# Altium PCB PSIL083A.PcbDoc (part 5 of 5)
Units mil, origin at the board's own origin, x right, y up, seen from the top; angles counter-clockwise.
Board outline 8750 x 2700 mil, 4 copper layers (Top Layer, Signal Layer 1, Signal Layer 2, Bottom Layer), stack 61.2 mil thick; 463 components, 395 nets, 2267 pads, 745 vias.
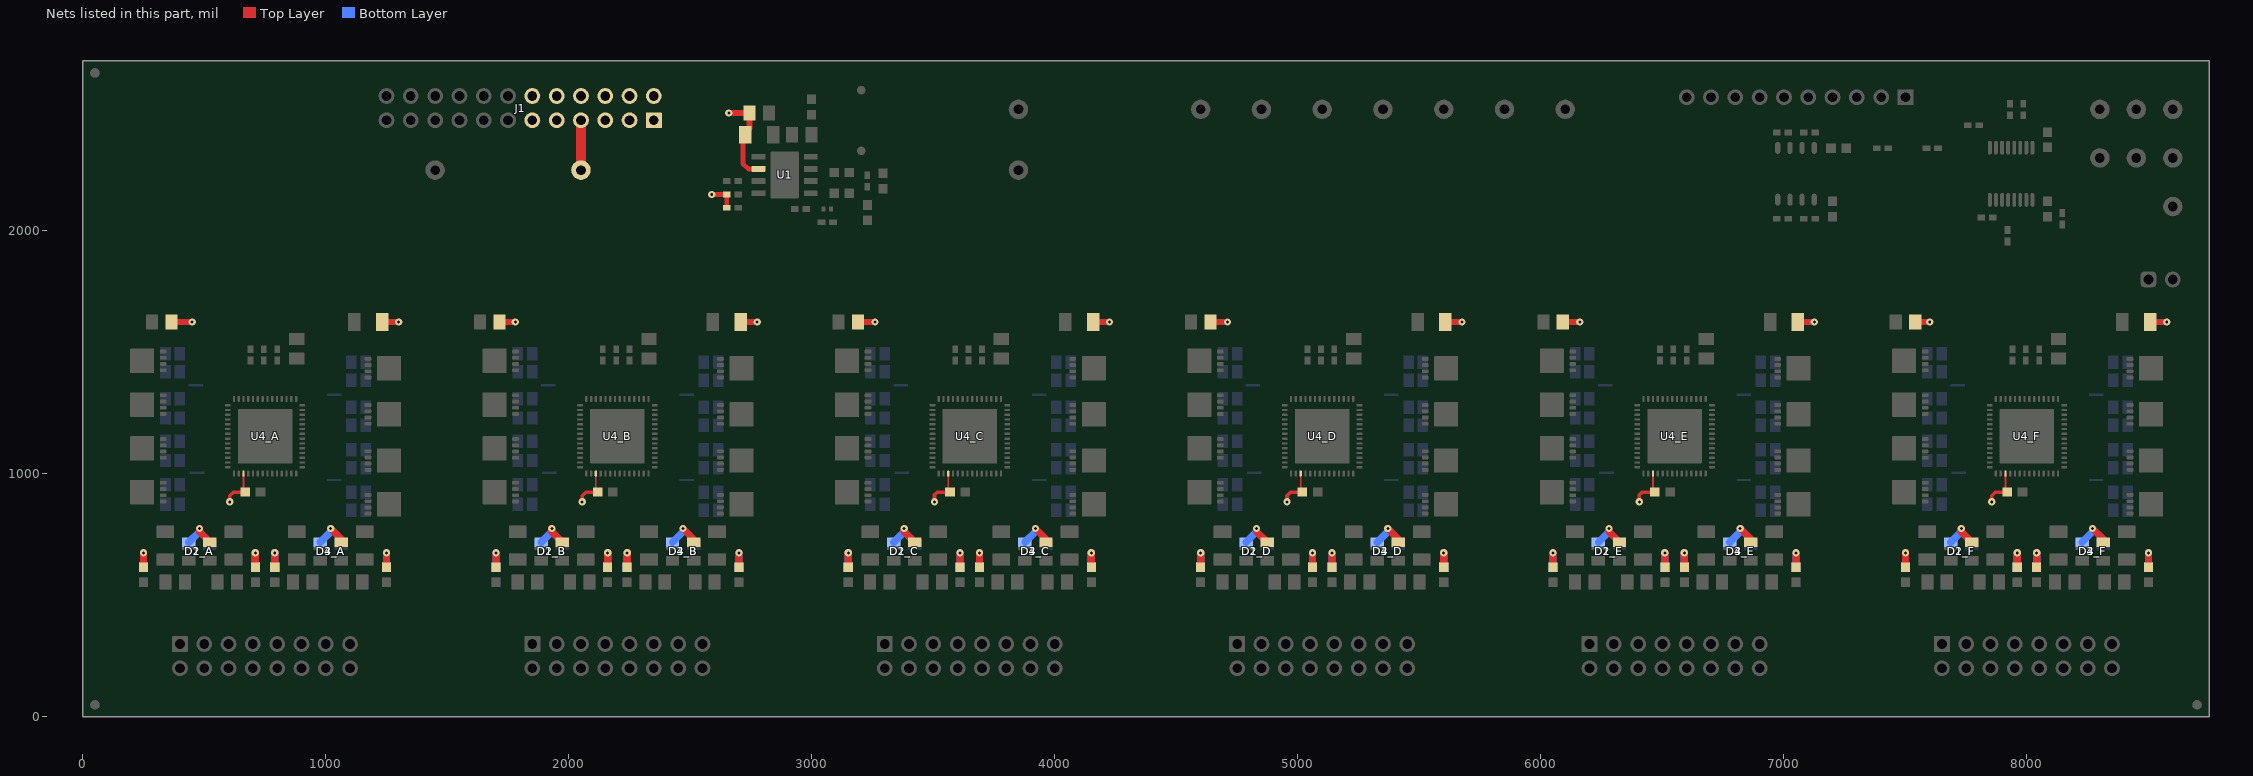
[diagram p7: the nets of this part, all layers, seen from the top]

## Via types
v1: diameter 30, hole 12, Top Layer to Bottom Layer, 610 vias
v2: diameter 19.68, hole 7.87, Top Layer to Bottom Layer, 130 vias
v3: diameter 19.68, hole 7.87, Top Layer to Bottom Layer, tented both sides, 4 vias
v4: diameter 34, hole 16, Top Layer to Bottom Layer, 1 vias

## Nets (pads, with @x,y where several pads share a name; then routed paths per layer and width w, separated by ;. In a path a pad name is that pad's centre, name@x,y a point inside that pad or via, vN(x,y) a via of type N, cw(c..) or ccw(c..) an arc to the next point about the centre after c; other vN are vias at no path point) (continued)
VPWR: C2.2 C3.2 C4.2 C5.2 C13_A.1 C13_B.1 C13_C.1 C13_D.1 C13_E.1 C13_F.1 C25.2 C26.2 C27.2 C28.2 C29.2 C30.2 C31.2 C32.2 C33.2 C34.2 D1_A.4 D1_B.4 D1_C.4 D1_D.4 D1_E.4 D1_F.4 D2_A.4 D2_B.4 D2_C.4 D2_D.4 D2_E.4 D2_F.4 D3_A.4 D3_B.4 D3_C.4 D3_D.4 D3_E.4 D3_F.4 D4_A.4 D4_B.4 D4_C.4 D4_D.4 D4_E.4 D4_F.4 J1.1 J1.2 J1.3 J1.4 J1.5 J1.6 J1.7 J1.8 J1.9 J1.10 J1.11 J1.12 L2_A.1 L2_B.1 L2_C.1 L2_D.1 L2_E.1 L2_F.1 L3_A.1 L3_B.1 L3_C.1 L3_D.1 L3_E.1 L3_F.1 L4_A.1 L4_B.1 L4_C.1 L4_D.1 L4_E.1 L4_F.1 L5_A.1 L5_B.1 L5_C.1 L5_D.1 L5_E.1 L5_F.1 L6_A.1 L6_B.1 L6_C.1 L6_D.1 L6_E.1 L6_F.1 L7_A.1 L7_B.1 L7_C.1 L7_D.1 L7_E.1 L7_F.1 L8_A.1 L8_B.1 L8_C.1 L8_D.1 L8_E.1 L8_F.1 L9_A.1 L9_B.1 L9_C.1 L9_D.1 L9_E.1 L9_F.1 R1.1 R2.1 TP1.1 U1.2 U4_A.17 U4_B.17 U4_C.17 U4_D.17 U4_E.17 U4_F.17 | length 7036.7
  Top Layer w7: U4_A.17@661.42,1001.46 661.42,932.09 C13_A.1@668.5,925 ; U4_B.17@2111.42,1001.46 2111.42,932.09 C13_B.1@2118.5,925 ; U4_C.17@3561.42,1001.46 3561.42,932.09 C13_C.1@3568.5,925 ; U4_D.17@5011.42,1001.46 5011.42,932.09 C13_D.1@5018.5,925 ; U4_E.17@6461.42,1001.46 6461.42,932.09 C13_E.1@6468.5,925 ; U4_F.17@7911.42,1001.46 7911.42,932.09 C13_F.1@7918.5,925
  Top Layer w15: v1(605,885) 605,910 620,925 C13_A.1@668.5,925 ; v1(2055,885) 2055,910 2070,925 C13_B.1@2118.5,925 ; v1(3505,885) 3505,914.51 3515.49,925 C13_C.1@3568.5,925 ; v1(4955,885) 4955,910 4970,925 C13_D.1@5018.5,925 ; v1(6405,885) 6405,914.51 6415.49,925 C13_E.1@6468.5,925 ; v1(7855,885) 7855,910 7870,925 C13_F.1@7918.5,925
  Top Layer w20: v1(2588.31,2150) R2.1@2649.69,2150 R1.1@2649.69,2095 ; C5.2@2716.38,2395 2716.38,2276.93 2738.31,2255 U1.2@2781.02,2255
  Top Layer w25: C3.2@365,1625 v1(450,1625) ; C2.2@1241.93,1625 v1(1300,1625) ; C26.2@1715,1625 v1(1780,1625) ; v1(2658.31,2485) C4.2@2743.31,2485 2743.31,2421.93 C5.2@2716.38,2395 ; C25.2@2716.93,1625 v1(2775,1625) ; C28.2@3190,1625 v1(3260,1625) ; C27.2@4166.93,1625 v1(4225,1625) ; C30.2@4640,1625 v1(4710,1625) ; C29.2@5616.93,1625 v1(5675,1625) ; C32.2@6090,1625 v1(6160,1625) ; C31.2@7066.93,1625 v1(7125,1625) ; C34.2@7540,1625 v1(7600,1625) ; C33.2@8516.93,1625 v1(8575,1625)
  Top Layer w30: L4_A.1@250,616.5 v1(250,675) ; v1(480,775) 480,761.61 D2_A.4@523.31,718.31 ; L5_A.1@710,616.5 v1(710,675) ; L8_A.1@790,616.5 v1(790,675) ; v1(1020,775) 1063.31,731.69 D4_A.4@1063.31,718.31 ; L9_A.1@1250,616.5 v1(1250,675) ; L4_B.1@1700,616.5 v1(1700,675) ; v1(1930,775) 1930,761.61 D2_B.4@1973.31,718.31 ; L5_B.1@2160,616.5 v1(2160,675) ; L8_B.1@2240,616.5 v1(2240,675) ; v1(2470,775) 2513.31,731.69 D4_B.4@2513.31,718.31 ; L9_B.1@2700,616.5 v1(2700,675) ; L4_C.1@3150,616.5 v1(3150,675) ; v1(3380,775) 3380,761.61 D2_C.4@3423.31,718.31 ; L5_C.1@3610,616.5 v1(3610,675) ; L8_C.1@3690,616.5 v1(3690,675) ; v1(3920,775) 3963.31,731.69 D4_C.4@3963.31,718.31 ; L9_C.1@4150,616.5 v1(4150,675) ; L4_D.1@4600,616.5 v1(4600,675) ; v1(4830,775) 4830,761.61 D2_D.4@4873.31,718.31 ; L5_D.1@5060,616.5 v1(5060,675) ; L8_D.1@5140,616.5 v1(5140,675) ; v1(5370,775) 5413.31,731.69 D4_D.4@5413.31,718.31 ; L9_D.1@5600,616.5 v1(5600,675) ; L4_E.1@6050,616.5 v1(6050,675) ; v1(6280,775) 6280,761.61 D2_E.4@6323.31,718.31 ; L5_E.1@6510,616.5 v1(6510,675) ; L8_E.1@6590,616.5 v1(6590,675) ; v1(6820,775) 6863.31,731.69 D4_E.4@6863.31,718.31 ; L9_E.1@7050,616.5 v1(7050,675) ; L4_F.1@7500,616.5 v1(7500,675) ; v1(7730,775) 7730,761.61 D2_F.4@7773.31,718.31 ; L5_F.1@7960,616.5 v1(7960,675) ; L8_F.1@8040,616.5 v1(8040,675) ; v1(8270,775) 8313.31,731.69 D4_F.4@8313.31,718.31 ; L9_F.1@8500,616.5 v1(8500,675)
  Top Layer w40: TP1.1@2050,2250 J1.7@2050,2455
  Bottom Layer w30: L3_A.1@250,616.5 v1(250,675) ; D1_A.4@436.69,718.31 v1@480,761.61 ; L2_A.1@710,616.5 v1(710,675) ; L7_A.1@790,616.5 v1(790,675) ; D3_A.4@976.69,718.31 1020,761.61 v1(1020,775) ; L6_A.1@1250,616.5 v1(1250,675) ; L3_B.1@1700,616.5 v1(1700,675) ; D1_B.4@1886.69,718.31 v1@1930,761.61 ; L2_B.1@2160,616.5 v1(2160,675) ; L7_B.1@2240,616.5 v1(2240,675) ; D3_B.4@2426.69,718.31 2470,761.61 v1(2470,775) ; L6_B.1@2700,616.5 v1(2700,675) ; L3_C.1@3150,616.5 v1(3150,675) ; D1_C.4@3336.69,718.31 v1@3380,761.61 ; L2_C.1@3610,616.5 v1(3610,675) ; L7_C.1@3690,616.5 v1(3690,675) ; D3_C.4@3876.69,718.31 3920,761.61 v1(3920,775) ; L6_C.1@4150,616.5 v1(4150,675) ; L3_D.1@4600,616.5 v1(4600,675) ; D1_D.4@4786.69,718.31 v1@4830,761.61 ; L2_D.1@5060,616.5 v1(5060,675) ; L7_D.1@5140,616.5 v1(5140,675) ; D3_D.4@5326.69,718.31 5370,761.61 v1(5370,775) ; L6_D.1@5600,616.5 v1(5600,675) ; L3_E.1@6050,616.5 v1(6050,675) ; D1_E.4@6236.69,718.31 v1@6280,761.61 ; L2_E.1@6510,616.5 v1(6510,675) ; L7_E.1@6590,616.5 v1(6590,675) ; D3_E.4@6776.69,718.31 6820,761.61 v1(6820,775) ; L6_E.1@7050,616.5 v1(7050,675) ; L3_F.1@7500,616.5 v1(7500,675) ; D1_F.4@7686.69,718.31 v1@7730,761.61 ; L2_F.1@7960,616.5 v1(7960,675) ; L7_F.1@8040,616.5 v1(8040,675) ; D3_F.4@8226.69,718.31 8270,761.61 v1(8270,775) ; L6_F.1@8500,616.5 v1(8500,675)
pads on no net: FID1.1 FID2.1 FID3.1 FID4.1 FID5.1 FID6.1 J4.8 LBL1.0 Q1_A.9@223.74,1426.61 Q1_A.9@223.74,1452.21 Q1_A.9@223.74,1477.8 Q1_A.9@223.74,1503.39 Q1_A.9@242.54,1438.92 Q1_A.9@242.54,1491.08 Q1_A.9@257.11,1465 Q1_A.9@278.17,1438.92 Q1_A.9@278.17,1491.08 Q1_B.9@1673.74,1426.61 Q1_B.9@1673.74,1452.21 Q1_B.9@1673.74,1477.8 Q1_B.9@1673.74,1503.39 Q1_B.9@1692.54,1438.92 Q1_B.9@1692.54,1491.08 Q1_B.9@1707.11,1465 Q1_B.9@1728.17,1438.92 Q1_B.9@1728.17,1491.08 Q1_C.9@3123.74,1426.61 Q1_C.9@3123.74,1452.21 Q1_C.9@3123.74,1477.8 Q1_C.9@3123.74,1503.39 Q1_C.9@3142.54,1438.92 Q1_C.9@3142.54,1491.08 Q1_C.9@3157.11,1465 Q1_C.9@3178.17,1438.92 Q1_C.9@3178.17,1491.08 Q1_D.9@4573.74,1426.61 Q1_D.9@4573.74,1452.21 Q1_D.9@4573.74,1477.8 Q1_D.9@4573.74,1503.39 Q1_D.9@4592.54,1438.92 Q1_D.9@4592.54,1491.08 Q1_D.9@4607.11,1465 Q1_D.9@4628.17,1438.92 Q1_D.9@4628.17,1491.08 Q1_E.9@6023.74,1426.61 Q1_E.9@6023.74,1452.21 Q1_E.9@6023.74,1477.8 Q1_E.9@6023.74,1503.39 Q1_E.9@6042.54,1438.92 Q1_E.9@6042.54,1491.08 Q1_E.9@6057.11,1465 Q1_E.9@6078.17,1438.92 Q1_E.9@6078.17,1491.08 Q1_F.9@7473.74,1426.61 Q1_F.9@7473.74,1452.21 Q1_F.9@7473.74,1477.8 Q1_F.9@7473.74,1503.39 Q1_F.9@7492.54,1438.92 Q1_F.9@7492.54,1491.08 Q1_F.9@7507.11,1465 Q1_F.9@7528.17,1438.92 Q1_F.9@7528.17,1491.08 Q2_A.9@223.74,1246.61 Q2_A.9@223.74,1272.21 Q2_A.9@223.74,1297.8 Q2_A.9@223.74,1323.39 Q2_A.9@242.54,1258.92 Q2_A.9@242.54,1311.08 Q2_A.9@257.11,1285 Q2_A.9@278.17,1258.92 Q2_A.9@278.17,1311.08 Q2_B.9@1673.74,1246.61 Q2_B.9@1673.74,1272.21 Q2_B.9@1673.74,1297.8 Q2_B.9@1673.74,1323.39 Q2_B.9@1692.54,1258.92 Q2_B.9@1692.54,1311.08 Q2_B.9@1707.11,1285 Q2_B.9@1728.17,1258.92 Q2_B.9@1728.17,1311.08 Q2_C.9@3123.74,1246.61 Q2_C.9@3123.74,1272.21 Q2_C.9@3123.74,1297.8 Q2_C.9@3123.74,1323.39 Q2_C.9@3142.54,1258.92 Q2_C.9@3142.54,1311.08 Q2_C.9@3157.11,1285 Q2_C.9@3178.17,1258.92 Q2_C.9@3178.17,1311.08 Q2_D.9@4573.74,1246.61 Q2_D.9@4573.74,1272.21 Q2_D.9@4573.74,1297.8 Q2_D.9@4573.74,1323.39 Q2_D.9@4592.54,1258.92 Q2_D.9@4592.54,1311.08 Q2_D.9@4607.11,1285 Q2_D.9@4628.17,1258.92 Q2_D.9@4628.17,1311.08 Q2_E.9@6023.74,1246.61 Q2_E.9@6023.74,1272.21 Q2_E.9@6023.74,1297.8 Q2_E.9@6023.74,1323.39 Q2_E.9@6042.54,1258.92 Q2_E.9@6042.54,1311.08 Q2_E.9@6057.11,1285 Q2_E.9@6078.17,1258.92 Q2_E.9@6078.17,1311.08 Q2_F.9@7473.74,1246.61 Q2_F.9@7473.74,1272.21 Q2_F.9@7473.74,1297.8 Q2_F.9@7473.74,1323.39 Q2_F.9@7492.54,1258.92 Q2_F.9@7492.54,1311.08 Q2_F.9@7507.11,1285 Q2_F.9@7528.17,1258.92 Q2_F.9@7528.17,1311.08 Q3_A.9@1226.83,848.92 Q3_A.9@1226.83,901.08 Q3_A.9@1247.89,875 Q3_A.9@1262.46,848.92 Q3_A.9@1262.46,901.08 Q3_A.9@1281.26,836.61 Q3_A.9@1281.26,862.21 Q3_A.9@1281.26,887.8 Q3_A.9@1281.26,913.39 Q3_B.9@2676.83,848.92 Q3_B.9@2676.83,901.08 Q3_B.9@2697.89,875 Q3_B.9@2712.46,848.92 Q3_B.9@2712.46,901.08 Q3_B.9@2731.26,836.61 Q3_B.9@2731.26,862.21 Q3_B.9@2731.26,887.8 Q3_B.9@2731.26,913.39 Q3_C.9@4126.83,848.92 Q3_C.9@4126.83,901.08 Q3_C.9@4147.89,875 Q3_C.9@4162.46,848.92 Q3_C.9@4162.46,901.08 Q3_C.9@4181.26,836.61 Q3_C.9@4181.26,862.21 Q3_C.9@4181.26,887.8 Q3_C.9@4181.26,913.39 Q3_D.9@5576.83,848.92 Q3_D.9@5576.83,901.08 Q3_D.9@5597.89,875 Q3_D.9@5612.46,848.92 Q3_D.9@5612.46,901.08 Q3_D.9@5631.26,836.61 Q3_D.9@5631.26,862.21 Q3_D.9@5631.26,887.8 Q3_D.9@5631.26,913.39 Q3_E.9@7026.83,848.92 Q3_E.9@7026.83,901.08 Q3_E.9@7047.89,875 Q3_E.9@7062.46,848.92 Q3_E.9@7062.46,901.08 Q3_E.9@7081.26,836.61 Q3_E.9@7081.26,862.21 Q3_E.9@7081.26,887.8 Q3_E.9@7081.26,913.39 Q3_F.9@8476.83,848.92 Q3_F.9@8476.83,901.08 Q3_F.9@8497.89,875 Q3_F.9@8512.46,848.92 Q3_F.9@8512.46,901.08 Q3_F.9@8531.26,836.61 Q3_F.9@8531.26,862.21 Q3_F.9@8531.26,887.8 Q3_F.9@8531.26,913.39 Q4_A.9@1226.83,1028.92 Q4_A.9@1226.83,1081.08 Q4_A.9@1247.89,1055 Q4_A.9@1262.46,1028.92 Q4_A.9@1262.46,1081.08 Q4_A.9@1281.26,1016.61 Q4_A.9@1281.26,1042.21 Q4_A.9@1281.26,1067.8 Q4_A.9@1281.26,1093.39 Q4_B.9@2676.83,1028.92 Q4_B.9@2676.83,1081.08 Q4_B.9@2697.89,1055 Q4_B.9@2712.46,1028.92 Q4_B.9@2712.46,1081.08 Q4_B.9@2731.26,1016.61 Q4_B.9@2731.26,1042.21 Q4_B.9@2731.26,1067.8 Q4_B.9@2731.26,1093.39 Q4_C.9@4126.83,1028.92 Q4_C.9@4126.83,1081.08 Q4_C.9@4147.89,1055 Q4_C.9@4162.46,1028.92 Q4_C.9@4162.46,1081.08 Q4_C.9@4181.26,1016.61 Q4_C.9@4181.26,1042.21 Q4_C.9@4181.26,1067.8 Q4_C.9@4181.26,1093.39 Q4_D.9@5576.83,1028.92 Q4_D.9@5576.83,1081.08 Q4_D.9@5597.89,1055 Q4_D.9@5612.46,1028.92 Q4_D.9@5612.46,1081.08 Q4_D.9@5631.26,1016.61 Q4_D.9@5631.26,1042.21 Q4_D.9@5631.26,1067.8 Q4_D.9@5631.26,1093.39 Q4_E.9@7026.83,1028.92 Q4_E.9@7026.83,1081.08 Q4_E.9@7047.89,1055 Q4_E.9@7062.46,1028.92 Q4_E.9@7062.46,1081.08 Q4_E.9@7081.26,1016.61 Q4_E.9@7081.26,1042.21 Q4_E.9@7081.26,1067.8 Q4_E.9@7081.26,1093.39 Q4_F.9@8476.83,1028.92 Q4_F.9@8476.83,1081.08 Q4_F.9@8497.89,1055 Q4_F.9@8512.46,1028.92 Q4_F.9@8512.46,1081.08 Q4_F.9@8531.26,1016.61 Q4_F.9@8531.26,1042.21 Q4_F.9@8531.26,1067.8 Q4_F.9@8531.26,1093.39 Q5_A.9@223.74,1066.61 Q5_A.9@223.74,1092.21 Q5_A.9@223.74,1117.8 Q5_A.9@223.74,1143.39 Q5_A.9@242.54,1078.92 Q5_A.9@242.54,1131.08 Q5_A.9@257.11,1105 Q5_A.9@278.17,1078.92 Q5_A.9@278.17,1131.08 Q5_B.9@1673.74,1066.61 Q5_B.9@1673.74,1092.21 Q5_B.9@1673.74,1117.8 Q5_B.9@1673.74,1143.39 Q5_B.9@1692.54,1078.92 Q5_B.9@1692.54,1131.08 Q5_B.9@1707.11,1105 Q5_B.9@1728.17,1078.92 Q5_B.9@1728.17,1131.08 Q5_C.9@3123.74,1066.61 Q5_C.9@3123.74,1092.21 Q5_C.9@3123.74,1117.8 Q5_C.9@3123.74,1143.39 Q5_C.9@3142.54,1078.92 Q5_C.9@3142.54,1131.08 Q5_C.9@3157.11,1105 Q5_C.9@3178.17,1078.92 Q5_C.9@3178.17,1131.08 Q5_D.9@4573.74,1066.61 Q5_D.9@4573.74,1092.21 Q5_D.9@4573.74,1117.8 Q5_D.9@4573.74,1143.39 Q5_D.9@4592.54,1078.92 Q5_D.9@4592.54,1131.08 Q5_D.9@4607.11,1105 Q5_D.9@4628.17,1078.92 Q5_D.9@4628.17,1131.08 Q5_E.9@6023.74,1066.61 Q5_E.9@6023.74,1092.21 Q5_E.9@6023.74,1117.8 Q5_E.9@6023.74,1143.39 Q5_E.9@6042.54,1078.92 Q5_E.9@6042.54,1131.08 Q5_E.9@6057.11,1105 Q5_E.9@6078.17,1078.92 Q5_E.9@6078.17,1131.08 Q5_F.9@7473.74,1066.61 Q5_F.9@7473.74,1092.21 Q5_F.9@7473.74,1117.8 Q5_F.9@7473.74,1143.39 Q5_F.9@7492.54,1078.92 Q5_F.9@7492.54,1131.08 Q5_F.9@7507.11,1105 Q5_F.9@7528.17,1078.92 Q5_F.9@7528.17,1131.08 Q6_A.9@223.74,886.61 Q6_A.9@223.74,912.21 Q6_A.9@223.74,937.8 Q6_A.9@223.74,963.39 Q6_A.9@242.54,898.92 Q6_A.9@242.54,951.08 Q6_A.9@257.11,925 Q6_A.9@278.17,898.92 Q6_A.9@278.17,951.08 Q6_B.9@1673.74,886.61 Q6_B.9@1673.74,912.21 Q6_B.9@1673.74,937.8 Q6_B.9@1673.74,963.39 Q6_B.9@1692.54,898.92 Q6_B.9@1692.54,951.08 Q6_B.9@1707.11,925 Q6_B.9@1728.17,898.92 Q6_B.9@1728.17,951.08 Q6_C.9@3123.74,886.61 Q6_C.9@3123.74,912.21 Q6_C.9@3123.74,937.8 Q6_C.9@3123.74,963.39 Q6_C.9@3142.54,898.92 Q6_C.9@3142.54,951.08 Q6_C.9@3157.11,925 Q6_C.9@3178.17,898.92 Q6_C.9@3178.17,951.08 Q6_D.9@4573.74,886.61 Q6_D.9@4573.74,912.21 Q6_D.9@4573.74,937.8 Q6_D.9@4573.74,963.39 Q6_D.9@4592.54,898.92 Q6_D.9@4592.54,951.08 Q6_D.9@4607.11,925 Q6_D.9@4628.17,898.92 Q6_D.9@4628.17,951.08 Q6_E.9@6023.74,886.61 Q6_E.9@6023.74,912.21 Q6_E.9@6023.74,937.8 Q6_E.9@6023.74,963.39 Q6_E.9@6042.54,898.92 Q6_E.9@6042.54,951.08 Q6_E.9@6057.11,925 Q6_E.9@6078.17,898.92 Q6_E.9@6078.17,951.08 Q6_F.9@7473.74,886.61 Q6_F.9@7473.74,912.21 Q6_F.9@7473.74,937.8 Q6_F.9@7473.74,963.39 Q6_F.9@7492.54,898.92 Q6_F.9@7492.54,951.08 Q6_F.9@7507.11,925 Q6_F.9@7528.17,898.92 Q6_F.9@7528.17,951.08 Q7_A.9@1226.83,1218.92 Q7_A.9@1226.83,1271.08 Q7_A.9@1247.89,1245 Q7_A.9@1262.46,1218.92 Q7_A.9@1262.46,1271.08 Q7_A.9@1281.26,1206.61 Q7_A.9@1281.26,1232.21 Q7_A.9@1281.26,1257.8 Q7_A.9@1281.26,1283.39 Q7_B.9@2676.83,1218.92 Q7_B.9@2676.83,1271.08 Q7_B.9@2697.89,1245 Q7_B.9@2712.46,1218.92 Q7_B.9@2712.46,1271.08 Q7_B.9@2731.26,1206.61 Q7_B.9@2731.26,1232.21 Q7_B.9@2731.26,1257.8 Q7_B.9@2731.26,1283.39 Q7_C.9@4126.83,1218.92 Q7_C.9@4126.83,1271.08 Q7_C.9@4147.89,1245 Q7_C.9@4162.46,1218.92 Q7_C.9@4162.46,1271.08 Q7_C.9@4181.26,1206.61 Q7_C.9@4181.26,1232.21 Q7_C.9@4181.26,1257.8 Q7_C.9@4181.26,1283.39 Q7_D.9@5576.83,1218.92 Q7_D.9@5576.83,1271.08 Q7_D.9@5597.89,1245 Q7_D.9@5612.46,1218.92 Q7_D.9@5612.46,1271.08 Q7_D.9@5631.26,1206.61 Q7_D.9@5631.26,1232.21 Q7_D.9@5631.26,1257.8 Q7_D.9@5631.26,1283.39 Q7_E.9@7026.83,1218.92 Q7_E.9@7026.83,1271.08 Q7_E.9@7047.89,1245 Q7_E.9@7062.46,1218.92 Q7_E.9@7062.46,1271.08 Q7_E.9@7081.26,1206.61 Q7_E.9@7081.26,1232.21 Q7_E.9@7081.26,1257.8 Q7_E.9@7081.26,1283.39 Q7_F.9@8476.83,1218.92 Q7_F.9@8476.83,1271.08 Q7_F.9@8497.89,1245 Q7_F.9@8512.46,1218.92 Q7_F.9@8512.46,1271.08 Q7_F.9@8531.26,1206.61 Q7_F.9@8531.26,1232.21 Q7_F.9@8531.26,1257.8 Q7_F.9@8531.26,1283.39 Q8_A.9@1226.83,1408.92 Q8_A.9@1226.83,1461.08 Q8_A.9@1247.89,1435 Q8_A.9@1262.46,1408.92 Q8_A.9@1262.46,1461.08 Q8_A.9@1281.26,1396.61 Q8_A.9@1281.26,1422.21 Q8_A.9@1281.26,1447.8 Q8_A.9@1281.26,1473.39 Q8_B.9@2676.83,1408.92 Q8_B.9@2676.83,1461.08 Q8_B.9@2697.89,1435 Q8_B.9@2712.46,1408.92 Q8_B.9@2712.46,1461.08 Q8_B.9@2731.26,1396.61 Q8_B.9@2731.26,1422.21 Q8_B.9@2731.26,1447.8 Q8_B.9@2731.26,1473.39 Q8_C.9@4126.83,1408.92 Q8_C.9@4126.83,1461.08 Q8_C.9@4147.89,1435 Q8_C.9@4162.46,1408.92 Q8_C.9@4162.46,1461.08 Q8_C.9@4181.26,1396.61 Q8_C.9@4181.26,1422.21 Q8_C.9@4181.26,1447.8 Q8_C.9@4181.26,1473.39 Q8_D.9@5576.83,1408.92 Q8_D.9@5576.83,1461.08 Q8_D.9@5597.89,1435 Q8_D.9@5612.46,1408.92 Q8_D.9@5612.46,1461.08 Q8_D.9@5631.26,1396.61 Q8_D.9@5631.26,1422.21 Q8_D.9@5631.26,1447.8 Q8_D.9@5631.26,1473.39 Q8_E.9@7026.83,1408.92 Q8_E.9@7026.83,1461.08 Q8_E.9@7047.89,1435 Q8_E.9@7062.46,1408.92 Q8_E.9@7062.46,1461.08 Q8_E.9@7081.26,1396.61 Q8_E.9@7081.26,1422.21 Q8_E.9@7081.26,1447.8 Q8_E.9@7081.26,1473.39 Q8_F.9@8476.83,1408.92 Q8_F.9@8476.83,1461.08 Q8_F.9@8497.89,1435 Q8_F.9@8512.46,1408.92 Q8_F.9@8512.46,1461.08 Q8_F.9@8531.26,1396.61 Q8_F.9@8531.26,1422.21 Q8_F.9@8531.26,1447.8 Q8_F.9@8531.26,1473.39 SH-J1.0 U1.9@2888.31,2230 U2.6 U2.11 U4_A.57@670.28,1075.28 U4_A.57@670.28,1128.43 U4_A.57@670.28,1181.58 U4_A.57@670.28,1234.72 U4_A.57@723.43,1075.28 U4_A.57@723.43,1128.43 U4_A.57@723.43,1181.58 U4_A.57@723.43,1234.72 U4_A.57@776.58,1075.28 U4_A.57@776.58,1128.43 U4_A.57@776.58,1181.58 U4_A.57@776.58,1234.72 U4_A.57@829.72,1075.28 U4_A.57@829.72,1128.43 U4_A.57@829.72,1181.58 U4_A.57@829.72,1234.72 U4_B.57@2120.28,1075.28 U4_B.57@2120.28,1128.43 U4_B.57@2120.28,1181.58 U4_B.57@2120.28,1234.72 U4_B.57@2173.43,1075.28 U4_B.57@2173.43,1128.43 U4_B.57@2173.43,1181.58 U4_B.57@2173.43,1234.72 U4_B.57@2226.57,1075.28 U4_B.57@2226.57,1128.43 U4_B.57@2226.57,1181.58 U4_B.57@2226.57,1234.72 U4_B.57@2279.72,1075.28 U4_B.57@2279.72,1128.43 U4_B.57@2279.72,1181.58 U4_B.57@2279.72,1234.72 U4_C.57@3570.28,1075.28 U4_C.57@3570.28,1128.43 U4_C.57@3570.28,1181.58 U4_C.57@3570.28,1234.72 U4_C.57@3623.43,1075.28 U4_C.57@3623.43,1128.43 U4_C.57@3623.43,1181.58 U4_C.57@3623.43,1234.72 U4_C.57@3676.57,1075.28 U4_C.57@3676.57,1128.43 U4_C.57@3676.57,1181.58 U4_C.57@3676.57,1234.72 U4_C.57@3729.72,1075.28 U4_C.57@3729.72,1128.43 U4_C.57@3729.72,1181.58 U4_C.57@3729.72,1234.72 U4_D.57@5020.28,1075.28 U4_D.57@5020.28,1128.43 U4_D.57@5020.28,1181.58 U4_D.57@5020.28,1234.72 U4_D.57@5073.43,1075.28 U4_D.57@5073.43,1128.43 U4_D.57@5073.43,1181.58 U4_D.57@5073.43,1234.72 U4_D.57@5126.57,1075.28 U4_D.57@5126.57,1128.43 U4_D.57@5126.57,1181.58 U4_D.57@5126.57,1234.72 U4_D.57@5179.72,1075.28 U4_D.57@5179.72,1128.43 U4_D.57@5179.72,1181.58 U4_D.57@5179.72,1234.72 U4_E.57@6470.28,1075.28 U4_E.57@6470.28,1128.43 U4_E.57@6470.28,1181.58 U4_E.57@6470.28,1234.72 U4_E.57@6523.43,1075.28 U4_E.57@6523.43,1128.43 U4_E.57@6523.43,1181.58 U4_E.57@6523.43,1234.72 U4_E.57@6576.57,1075.28 U4_E.57@6576.57,1128.43 U4_E.57@6576.57,1181.58 U4_E.57@6576.57,1234.72 U4_E.57@6629.72,1075.28 U4_E.57@6629.72,1128.43 U4_E.57@6629.72,1181.58 U4_E.57@6629.72,1234.72 U4_F.57@7920.28,1075.28 U4_F.57@7920.28,1128.43 U4_F.57@7920.28,1181.58 U4_F.57@7920.28,1234.72 U4_F.57@7973.43,1075.28 U4_F.57@7973.43,1128.43 U4_F.57@7973.43,1181.58 U4_F.57@7973.43,1234.72 U4_F.57@8026.58,1075.28 U4_F.57@8026.58,1128.43 U4_F.57@8026.58,1181.58 U4_F.57@8026.58,1234.72 U4_F.57@8079.72,1075.28 U4_F.57@8079.72,1128.43 U4_F.57@8079.72,1181.58 U4_F.57@8079.72,1234.72

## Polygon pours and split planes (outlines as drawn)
GND on Signal Layer 1 "SIGNAL_LAYER_1_GND_P004" (solid, remove dead copper, pour order 4): 8350,2155 8350,1950 8700,1950 8700,650 50,650 50,2650 6735,2650 6735,2155
GND_ISO on Signal Layer 1 "SIGNAL_LAYER_1_GND_ISO_P018" (solid, remove dead copper, pour order 18): 8200,2650 8200,2310 6865,2310 6865,2650
VPWR on Signal Layer 2 "SIGNAL_LAYER_2_VPWR_P002" (solid, remove dead copper, pour order 2): 8700,1950 8350,1950 8350,2155 6735,2155 6735,2650 50,2650 50,650 8700,650
3.3V_ISO on Signal Layer 2 "SIGNAL_LAYER_2_3.3V_ISO_P016" (solid, remove dead copper, pour order 16): 6865,2650 8200,2650 8200,2305 6865,2305
GND on Bottom Layer "BOTTOM_LAYER_GND_P006" (solid, remove dead copper, pour order 6): 8350,2155 8350,1950 8700,1950 8700,650 50,650 50,2650 6735,2650 6735,2155
GND_ISO on Bottom Layer "BOTTOM_LAYER_GND_ISO_P022" (solid, remove dead copper, pour order 22): 6865,2650 6865,2310 8200,2310 8200,2650
GND on Top Layer "TOP_LAYER_GND_P008" (solid, remove dead copper, pour order 8): 8350,2155 8350,1950 8700,1950 8700,650 50,650 50,2650 6735,2650 6735,2155
GND_ISO on Top Layer "TOP_LAYER_GND_ISO_P020" (solid, remove dead copper, pour order 20): 8200,2650 6865,2650 6865,2310 8200,2310

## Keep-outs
Keep-Out Layer:
  text ".Layer_Name" at 577,-858.49 h60

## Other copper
Top Layer:
  text ".Layer_Name" at 577,-858.49 h60
Signal Layer 1:
  text ".Layer_Name" at 560,-850 h60
Signal Layer 2:
  text ".Layer_Name" at 545,-855 h60
Bottom Layer:
  text ".Layer_Name" at 565,-835 h60

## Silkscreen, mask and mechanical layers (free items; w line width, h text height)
Top Overlay:
  text "'.PRJ_Number'.PCB_Rev" at 335,2275 h108.27
  text "P_SEL" at 8230,1780 h72.83
  text ".Layer_Name" at 577,-858.49 h60
Bottom Overlay:
  text ".Layer_Name" at 577,-858.49 h60
Top Paste:
  text ".Layer_Name" at 577,-858.49 h60
Bottom Paste:
  text ".Layer_Name" at 577,-858.49 h60
Top Solder:
  text ".Layer_Name" at 577,-858.49 h60
  text ".Layer_Name" at 577,-858.49 h60
Bottom Solder:
  text ".Layer_Name" at 577,-858.49 h60
Drill Guide:
  text ".Layer_Name" at 577,-858.49 h60
M1 Board Outline:
  the board outline again, w10
  text ".Layer_Name" at 577,-858.49 h60
M2 Board Dimensions:
  rectangle: 0,-275 125,-150
  rectangle: 125,-400 500,-275
  lines w7: 0,-275 1000,-275 ; 125,-400 125,-150 ; 250,-400 250,-150 ; 500,-400 500,-150 ; 750,-400 750,-150 ; 0,-400 1000,-400 1000,-150 0,-150 0,-400
  text ".Layer_Name" at 577,-858.49 h60
M3 3D STEP Top:
  text ".Layer_Name" at 577,-858.49 h60
M4 3D STEP Bottom:
  text ".Layer_Name" at 577,-858.49 h60
M5 Assembly Top:
  lines w10: -292,-930.17 6308,-930.17 ; -292,-726.83 6310,-726.83 ; -292,-523.5 -292,-1133.5 3713,-1133.5 6310,-1133.5 6310,-523.5 -291.5,-523.5 -291.5,-1133.5 1284,-1133.5 ; 2173,-1133.5 2173,-523.5 ; 3440,-726.83 3440,-523.5 ; 4280,-726.83 4280,-523.5 ; 4902,-1140 4902,-937.17
  text "COMPONENTS MARKED 'DNP' SHOULD NOT BE POPULATED." at 1153.5,-318.5 h60
  text "ASSEMBLY VARIANT:" at 1153,-434 h60
  text ".VariantName" at 2189,-434 h60
  text "PCB VIEWED FROM TOP SIDE" at -228.5,-655.67 h60
  text "BOARD #:" at 2248,-655.67 h60
  text ".PRJ_Number" at 2793.5,-655.67 h60
  text "REV:" at 3638,-655.67 h60
  text ".PCB_Rev" at 3929.5,-655.67 h60
  text "SVN REV:" at 4476,-655.67 h60
  text ".VersionControl_RevNumber" at 4982,-655.67 h60
  text "TID #:" at 2248,-859 h60
  text ".TID" at 2793.5,-859 h60
  text "PLOT NAME =" at -228.5,-1064.34 h60
  text ".plot_File_Name" at 577,-1064.34 h60
  text "GENERATED    :" at 2250,-1064.34 h60
  text ".Print_Date" at 3119.5,-1064.34 h60
  text ".Print_Time" at 3848.5,-1064.34 h60
  text "TEXAS INSTRUMENTS" at 5113,-1064.34 h60
M6 Assembly Bottom:
  lines w10: -292.5,-727.33 6309.5,-727.33 ; -290.5,-930.67 6309.5,-930.67 ; 1115.5,-1140.5 1115.5,-937.67 ; 1737.5,-727.33 1737.5,-524 ; 2577.5,-727.33 2577.5,-524 ; 3844.5,-1134 3844.5,-524 ; 4733.5,-1134 6309,-1134 6309,-524 -292.5,-524 -292.5,-1134 2304.5,-1134 6309.5,-1134 6309.5,-524
  text "COMPONENTS MARKED 'DNP' SHOULD NOT BE POPULATED." at 6102,-318 h60
  text ".VariantName" at 5058,-434 h60
  text "ASSEMBLY VARIANT:" at 6097,-434 h60
  text ".VersionControl_RevNumber" at 1035.5,-656.17 h60
  text "SVN REV:" at 1541.5,-656.17 h60
  text ".PCB_Rev" at 2088,-656.17 h60
  text "REV:" at 2379.5,-656.17 h60
  text ".PRJ_Number" at 3224,-656.17 h60
  text "BOARD #:" at 3769.5,-656.17 h60
  text "PCB VIEWED FROM BOTTOM SIDE" at 6246,-656.17 h60
  text ".TID" at 3224,-859.5 h60
  text "TID #:" at 3769.5,-859.5 h60
  text "TEXAS INSTRUMENTS" at 904.5,-1064.84 h60
  text ".Print_Time" at 2169,-1064.84 h60
  text ".Print_Date" at 2898,-1064.84 h60
  text "GENERATED    :" at 3767.5,-1064.84 h60
  text ".plot_File_Name" at 5440.5,-1064.84 h60
  text "PLOT NAME =" at 6246,-1064.84 h60
M9 Title Sheet:
  drawing of 57 lines, arcs and shapes, not listed
  text "1" at 739.84,8036.5 h70
  text "2" at 3235.5,8036.5 h70
  text "3" at 5724.84,8036.5 h70
  text "4" at 8231.51,8036.5 h70
  text "5" at 10730.5,8036.5 h70
  text "6" at 13235.5,8036.5 h70
  text "A" at -416.5,6893.5 h70
  text "A" at 14383.5,6893.5 h70
  text "B" at -416.5,4513.5 h70
  text "B" at 14383.5,4513.5 h70
  text "C" at -416.5,2138.5 h70
  text "C" at 14383.5,2138.5 h70
  text "PROJECT TITLE:" at 11343.5,277.5 h45
  text ".PRJ_Title" at 11393.5,144.17 h70
  text "DESIGNED FOR:" at 11343.5,-23.5 h45
  text ".PRJ_Customer" at 11393.5,-163.5 h70
  text "D" at -416.5,-231.5 h70
  text "D" at 14383.5,-231.5 h70
  text "FILE NAME:" at 11343.5,-323.5 h45
  text ".PCB_File_Name_No_Path" at 11393.5,-443.5 h70
  text "Texas Instruments (TI) and/or its licensors do not warrant the accuracy or completeness of this specification" at 6374,-605.34 h45
  text "ENGINEER:" at 11343.5,-613.5 h45
  text "LAYOUT BY:" at 12848.5,-613.5 h45
  text "or any information contained therein. TI and/or its licensors do not warrant that this design will meet" at 6329.01,-718 h45
  text ".PRJ_Engineer" at 11393.5,-768.49 h70
  text ".PCB_Layout" at 12899,-768.49 h70
  text "the specifications, will be suitable for your application or fit for any particular purpose, or will operate in" at 6329.01,-830.67 h45
  text ".Layer_Name" at 577,-858.49 h60
  text "ALTIUM DESIGNER VERSION:" at 12848.5,-923.5 h45
  text "an implementation. TI and/or its licensors do not warrant that the design is production worthy. You should" at 6329.01,-943.33 h45
  text "completely validate and test your design implementation to confirm the system functionality for your application." at 6374,-1056 h45
  text ".print_Scale" at 11393.5,-1056.83 h70
  text ".Application_BuildNumber" at 12899,-1056.83 h70
  text "1" at 739.84,-1263.5 h70
  text "2" at 3235.5,-1263.5 h70
  text "3" at 5724.84,-1263.5 h70
  text "4" at 8231.51,-1263.5 h70
  text "5" at 10730.5,-1263.5 h70
  text "6" at 13235.5,-1263.5 h70
M10 Fab Notes:
  drawing of 189 lines, arcs and shapes, not listed
  text "DESIGN INFORMATION" at 12382.02,6356.17 h60
  text "MIN. TRACK WIDTH:" at 11737.46,6224.05 h60
  text "7" at 12833.7,6224.05 h60
  text "MIL" at 12988.46,6224.05 h60
  text "MIN. CLEARANCE:" at 11737.46,6099.92 h60
  text "0.2" at 12773.7,6099.93 h60
  text "mm" at 12988.46,6099.92 h60
  text "MIN. VIA PAD SIZE:" at 11737.46,5975.8 h60
  text "24" at 12803.71,5975.8 h60
  text "MIL" at 12988.46,5975.8 h60
  text "0.05mm (2MIL)" at 12432.46,5845.9 h60
  text "MINIMUM ANNULAR RING" at 11408.23,5837.67 h60
  text "EXTERNAL" at 13140.46,5837.67 h60
  text "PER" at 11608.23,5727.55 h60
  text "IPC-D-275 CLASS 2 LEVEL C" at 11828.23,5727.54 h60
  text "MIL, HOLES" at 13316.46,5627.07 h60
  text "+/-" at 12924,5618.48 h60
  text "+/-" at 13778,5618.48 h60
  text "REGISTRATION TOLERANCES:" at 11408.23,5617.42 h60
  text "METAL" at 12608,5617.42 h60
  text "5" at 13184.2,5617.42 h60
  text "3" at 14017.2,5617.42 h60
  text "MIL" at 14133.46,5617.42 h60
  text "HOLE SIZE TOLERANCE (UNLESS OTHERWISE SPECIFIED):" at 11408.23,5519.1 h60
  text "+/-" at 13778,5516.23 h60
  text "3" at 14017.2,5515.17 h60
  text "MIL" at 14133.46,5515.17 h60
  text "MATERIAL:" at 11333.46,5377.52 h60
  text "FR-4 High Tg" at 12319.9,5249 h60
  text "X" at 12175.46,5241.01 h60
  text "FR-408" at 11754.46,5236.49 h60
  text "OTHER" at 13242.46,5236.49 h60
  text "62 MIL (1.6mm) +/-10%" at 12074.56,5093.46 h60
  text "X" at 11954.46,5091.01 h60
  text "THICKNESS:" at 11408.23,5085.24 h60
  text "OTHER" at 13359.46,5085.24 h60
  text "TOLERANCE:" at 11408.23,4946.92 h60
  text "X" at 12256.46,4946.92 h60
  text "ANSI IPC-6012 TYPE 3 CLASS 2" at 12434.48,4946.92 h60
  text "OTHER +/-" at 12434.46,4802.73 h60
  text "BOW & TWIST:" at 11408.23,4657.54 h60
  text "X" at 12256.46,4657.54 h60
  text "ANSI IPC-6012 TYPE 3 CLASS 2" at 12434.48,4657.54 h60
  text "OTHER +/-" at 12434.46,4510.85 h60
  text "DRILLING:" at 11333.46,4380.23 h60
  text "NC_DRILL FILES" at 13094.46,4275.04 h60
  text "REFERENCE:" at 11408.23,4271.1 h60
  text "X" at 12065.46,4271.01 h60
  text "AS SHOWN" at 12243.46,4271.1 h60
  text "X" at 12966.46,4271.1 h60
  text "OTHER" at 13392.46,4128.85 h60
  text "PTH COPPER THICKNESS:" at 11407.91,4125.32 h60
  text "X" at 12547.14,4125.32 h60
  text "20-30 um" at 12675.14,4125.32 h60
  text "BOARD FINISH:" at 11333.46,3977.73 h60
  text "SILKSCREEN:" at 11488.68,3867.6 h60
  text "X" at 12446.46,3867.6 h60
  text "TOP" at 12563.46,3867.6 h60
  text "X" at 12956.46,3867.6 h60
  text "BOTTOM" at 13074.46,3867.6 h60
  text "SILKSCREEN COLOR:" at 11488.68,3712.41 h60
  text "X" at 12445.46,3712.41 h60
  text "WHITE" at 12563.46,3712.41 h60
  text "OTHER" at 13074.46,3712.41 h60
  text "X" at 12576.46,3568.96 h60
  text "GREEN" at 12694.46,3568.96 h60
  text "OTHER" at 13312.46,3568.96 h60
  text "SOLDER RESIST COLOR:" at 11488.68,3562.1 h60
  text "X" at 12576.46,3414.71 h60
  text "MATTE" at 12694.46,3414.71 h60
  text "SEMI-GLOSS" at 13312,3414.07 h60
  text "IMMERSION GOLD (ENIG)" at 12394.46,3241.94 h60
  text "ENEPIG" at 13732,3234.72 h60
  text "SURFACE FINISH:" at 11333.46,3233.72 h60
  text "X" at 12216.46,3233.72 h60
  text "IMM. TIN/SILVER OR EQUIV" at 11663,3096.4 h60
  text "OTHER" at 13094.46,3092.47 h60
  text "ARRAY/PANEL:" at 11333.46,2937.09 h60
  text "X" at 12230,2930 h60
  text "CUT AND TRIM PER M1 BOARD OUTLINE" at 12394.46,2928.87 h60
  text "N.C. ROUTE" at 12394.46,2792.9 h60
  text "V. SCORE" at 13260.46,2792.9 h60
  text "CERTIFICATION:" at 11333.46,2663.77 h60
  text "MATERIALS AND WORKMANSHIP FOR ALL PCBS" at 12058.46,2663.77 h60
  text "TO MEET OR EXCEED THE REQUIREMENTS OF:" at 12058.46,2569.71 h60
  text "X" at 11695.97,2441.08 h60
  text "ANSI IPC-A-600F CLASS ->" at 11823.96,2441.08 h60
  text "X" at 13471.97,2441.08 h60
  text "2" at 13581.96,2441.08 h60
  text "1" at 13266.96,2439.58 h60
  text "3" at 13935.96,2439.58 h60
  text "X" at 12507.97,2293.39 h60
  text "RoHS" at 12635.96,2293.39 h60
  text "OTHER" at 13280.36,2293.39 h60
  text "PER ORDER" at 13677.42,2293.39 h60
  text "ALL BOARDS MUST MEET OR EXCEED UL94-V0 REQUIREMENTS." at 11361,2139.57 h60
  text "PCB MUST BEAR THE UL94V-0 UL REGISTERED MATERIAL ID NUMBER" at 11361,2023.5 h60
  text "ADDITIONAL REQUIREMENTS:" at 11333.46,1854.08 h60
  text "MICROSECTION:" at 11408.23,1746.95 h60
  text "YES" at 12313.96,1746.95 h60
  text "REQUIRED" at 13175.46,1602.62 h60
  text "BARE BOARD ELEC. TEST:" at 11408.23,1599.76 h60
  text "NONE" at 12713.96,1599.76 h60
  text "X" at 13057.46,1599.76 h60
  text "PER ORDER" at 13767.46,1599.76 h60
  text "XX MIL VIAS REQUIRE NON-CONDUCTIVE FILL AND PLANARIZE" at 11576.38,1394.82 h59
  text "XX MIL VIAS REQUIRE CONDUCTIVE FILL AND PLANARIZE" at 11584.38,1290.84 h60
  text "OUTER XX MIL TRACES REQUIRE 50 OHM SINGLE-ENDED IMPEDANCE" at 11583.39,1127.46 h58
  text "LAYER 2 & 3 (INNER LAYERS) XX MIL WIDE, XX MIL SPACE / TRACES REQUIRE 100 OHM DIFFERENTIAL IMPEDANCE" at 11575.39,891.74 h60
  text ".Layer_Name" at 577,-858.49 h60
M11 Gerber Information:
  lines w10: -292,-930.17 6308,-930.17 ; -292,-726.83 6310,-726.83 ; -292,-523.5 -292,-1133.5 3713,-1133.5 6310,-1133.5 6310,-523.5 -291.5,-523.5 -291.5,-1133.5 1284,-1133.5 ; 2173,-1133.5 2173,-523.5 ; 3440,-726.83 3440,-523.5 ; 4280,-726.83 4280,-523.5 ; 4902,-1140 4902,-937.17
  text "ALL ARTWORK VIEWED FROM TOP SIDE" at -228.5,-655.67 h60
  text "BOARD #:" at 2248,-655.67 h60
  text ".PRJ_Number" at 2793.5,-655.67 h60
  text "REV:" at 3638,-655.67 h60
  text ".PCB_Rev" at 3929.5,-655.67 h60
  text "SVN REV:" at 4476,-655.67 h60
  text ".VersionControl_RevNumber" at 4982,-655.67 h60
  text "LAYER NAME =" at -228.5,-858.49 h60
  text "TID #:" at 2248,-859 h60
  text ".TID" at 2793.5,-859 h60
  text "PLOT NAME =" at -228.5,-1064.34 h60
  text ".plot_File_Name" at 577,-1064.34 h60
  text "GENERATED    :" at 2250,-1064.34 h60
  text ".Print_Date" at 3119.5,-1064.34 h60
  text ".Print_Time" at 3848.5,-1064.34 h60
  text "TEXAS INSTRUMENTS" at 5113,-1064.34 h60
M12 Stackup:
  drawing of 295 lines, arcs and shapes, not listed
  text "Layer" at 9760.88,7839.68 h60
  text "Name" at 10170.8,7839.68 h60
  text "Material" at 11110.54,7839.68 h60
  text "Thickness" at 11970.3,7839.68 h60
  text "Constant" at 12620.14,7839.68 h60
  text "Board Layer Stack" at 13190,7839.68 h60
  text "1" at 9760.88,7719.68 h60
  text "Top Overlay" at 10170.8,7719.68 h60
  text "2" at 9760.88,7599.68 h60
  text "Top Solder" at 10170.8,7599.68 h60
  text "Solder Resist" at 11110.54,7599.68 h60
  text "0.40mil" at 11970.3,7599.68 h60
  text "3.5" at 12620.14,7599.68 h60
  text "3" at 9760.88,7479.68 h60
  text "Top Layer" at 10170.8,7479.68 h60
  text "Copper" at 11110.54,7479.68 h60
  text "2.80mil" at 11970.3,7479.68 h60
  text "4" at 9760.88,7359.68 h60
  text "Dielectric1" at 10170.8,7359.68 h60
  text "FR-4" at 11110.54,7359.68 h60
  text "20.00mil" at 11970.3,7359.68 h60
  text "4.2" at 12620.14,7359.68 h60
  text "5" at 9760.88,7239.68 h60
  text "Signal Layer 1" at 10170.8,7239.68 h60
  text "Copper" at 11110.54,7239.68 h60
  text "2.80mil" at 11970.3,7239.68 h60
  text "6" at 9760.88,7119.68 h60
  text "Dielectric 2" at 10170.8,7119.68 h60
  text "FR-4" at 11110.54,7119.68 h60
  text "10.00mil" at 11970.3,7119.68 h60
  text "4.2" at 12620.14,7119.68 h60
  text "7" at 9760.88,6999.68 h60
  text "Signal Layer 2" at 10170.8,6999.68 h60
  text "Copper" at 11110.54,6999.68 h60
  text "2.80mil" at 11970.3,6999.68 h60
  text "8" at 9760.88,6879.68 h60
  text "Dielectric 3" at 10170.8,6879.68 h60
  text "FR-4" at 11110.54,6879.68 h60
  text "20.00mil" at 11970.3,6879.68 h60
  text "4.2" at 12620.14,6879.68 h60
  text "9" at 9760.88,6759.68 h60
  text "Bottom Layer" at 10170.8,6759.68 h60
  text "Copper" at 11110.54,6759.68 h60
  text "2.80mil" at 11970.3,6759.68 h60
  text "10" at 9760.88,6639.68 h60
  text "Bottom Solder" at 10170.8,6639.68 h60
  text "Solder Resist" at 11110.54,6639.68 h60
  text "0.40mil" at 11970.3,6639.68 h60
  text "3.5" at 12620.14,6639.68 h60
  text "11" at 9760.88,6519.68 h60
  text "Bottom Overlay" at 10170.8,6519.68 h60
  text ".Layer_Name" at 577,-858.49 h60
M13 Component Bodies Top:
  text ".Layer_Name" at 577,-858.49 h60
M14 Component Bodies Bottom:
  text ".Layer_Name" at 577,-858.49 h60
M15 Courtyards Top:
  text ".Layer_Name" at 577,-858.49 h60
M16 Courtyards Bottom:
  text ".Layer_Name" at 577,-858.49 h60
Drill Drawing:
  circle w10: c5578.72,3246.96 r27.63
  lines w10: 5551.09,2970.7 5606.34,2970.7 5606.34,3025.95 5551.09,3025.95 5551.09,2970.7 ; 5551.09,3108.83 5564.9,3108.83 5578.72,3095.02 5592.53,3108.83 5606.34,3108.83 5592.53,3122.64 5606.34,3136.46 5592.53,3136.46 5578.72,3150.27 5564.9,3136.46 5551.09,3136.46 5564.9,3122.64 5551.09,3108.83 ; 5551.09,3398.91 5606.34,3398.91 5578.72,3343.66 5551.09,3398.91
  lines w12: 5501,2933.4 8732.49,2933.4 ; 5501,3430.68 8732.49,3430.68 ; 5838.86,2809.08 5838.86,3555 ; 6170.86,2809.08 6170.86,3555 ; 6807.43,2809.08 6807.43,3555 ; 7066.57,2809.08 7066.57,3555 ; 7441.72,2809.08 7441.72,3555 ; 8166.05,2809.08 8166.05,3555 ; 5501,2809.08 8732.49,2809.08 8732.49,3555 5501,3555 5501,2809.08
  text "Symbol" at 5575.59,3467.98 h72
  text "Quantity" at 5876.16,3467.98 h72
  text "Finished Hole Size" at 6208.16,3467.98 h72
  text "Plated" at 6844.72,3467.98 h72
  text "Hole Type" at 7103.86,3467.98 h72
  text "Drill Layer Pair" at 7479.02,3467.98 h72
  text "Hole Tolerance" at 8203.35,3467.98 h72
  text "134" at 5876.16,3343.66 h60
  text "7.87mil (0.200mm)" at 6208.16,3343.66 h60
  text "PTH" at 6844.72,3343.66 h60
  text "Round" at 7103.86,3343.66 h60
  text "Top Layer - Bottom Layer" at 7479.02,3343.66 h60
  text "610" at 5876.16,3219.34 h60
  text "12.00mil (0.305mm)" at 6208.16,3219.34 h60
  text "PTH" at 6844.72,3219.34 h60
  text "Round" at 7103.86,3219.34 h60
  text "Top Layer - Bottom Layer" at 7479.02,3219.34 h60
  text "1" at 5876.16,3095.02 h60
  text "16.00mil (0.406mm)" at 6208.16,3095.02 h60
  text "PTH" at 6844.72,3095.02 h60
  text "Round" at 7103.86,3095.02 h60
  text "Top Layer - Bottom Layer" at 7479.02,3095.02 h60
  text "150" at 5876.16,2970.7 h60
  text "40.00mil (1.016mm)" at 6208.16,2970.7 h60
  text "PTH" at 6844.72,2970.7 h60
  text "Round" at 7103.86,2970.7 h60
  text "Top Layer - Bottom Layer" at 7479.02,2970.7 h60
  text "895 Total" at 5876.16,2846.38 h60
  text ".Layer_Name" at 577,-858.49 h60
M17 Embedded Cavity:
  text ".Layer_Name" at 577,-858.49 h60
M18 Embedded Assembly:
  text ".Layer_Name" at 577,-858.49 h60
M19 Embedded Keepout:
  text ".Layer_Name" at 577,-858.49 h60

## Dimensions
0,-400 to 1000,-400 on M2 Board Dimensions
0,0 to 0,2700 on M2 Board Dimensions
0,0 to 8750,0 on M2 Board Dimensions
